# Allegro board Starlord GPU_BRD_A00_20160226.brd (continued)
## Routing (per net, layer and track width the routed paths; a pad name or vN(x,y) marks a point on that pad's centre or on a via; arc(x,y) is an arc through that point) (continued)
VCC1R05VIDEO_PEX_PLLVDD: length 11.2
  TOP w0.508: v2(17.95,59.36) 18.02,59.36 18.15,59.24 v1(20.36,59.24) 21.78,59.24 22.18,58.84 C7318.1 23.72,58.84 v2(24.04,58.52)
  BOTTOM w0.508: L7301.1 14.07,60.82 C7319.1 15.01,60.73 C7317.1 16.65,60.73 17.95,59.44 v2(17.95,59.36)
1D05V_PWR: length 19.8
  L3 w0.254: v2(3.44,63.3) 1.79,64.95 1.79,72.25 2.16,72.61 2.16,73.04 1.79,73.4 1.79,78.77 2.53,79.51 v2(3.22,79.51)
  BOTTOM w0.254: v2(3.22,79.51) PC8305.1 PR8303.1
  vias: v1(5.04,63.43)
1D05V_VGA_EN: length 99
  TOP w0.127: PR8310.2 C8308.2 36.59,3.58 v2(37.12,3.05) 37.15,3.08 37.71,3.08 v1(37.73,3.1)
  L3 w0.127: v2(1.44,72.75) 1.44,72.61 1.27,72.44 1.27,56.67 0.87,56.26 0.87,51.39 1.27,50.98 1.27,46.22 2.42,45.08 2.42,39.18 3.47,38.13 6.04,38.13 7.56,36.6 7.56,34.5 12.69,29.37 12.69,23.83 14.7,21.82 14.7,16.59 16.78,14.51 19.64,14.51 21.81,12.34 21.81,9.45 25.57,5.69 v2(25.57,5.36)
  L6 w0.127: v2(37.12,3.05) 36.16,3.05 35.74,2.63 28.3,2.63 v2(25.57,5.36)
  BOTTOM w0.127: v2(25.57,5.36) 25.57,5.54 25.52,5.59 R8305.2 ; PR8308.1 2.2,72.06 1.51,72.75 v2(1.44,72.75) ; PQ8301.2 37.07,3 v2(37.12,3.05)
1D05V_VGA_EN#:
  vias: v1(39.16,1.63)
1D05V_VGA_S0: length 87.2
  TOP w0.508: v2(37.2,4.75) 37.86,4.75 38.45,4.16 42.23,4.16 42.61,4.55 44.92,4.55 47.92,7.55 47.92,8.82 46.9,9.83 46.9,12.93 44.62,15.22 44.62,30.52 45.18,31.08 45.18,31.96 45.15,31.98 45.15,32.97 44.71,33.41 42.02,33.41 41.54,33.89 41.54,37.22 40.55,38.21 40.55,38.95 40.18,39.32 35.55,39.32 v2(35.32,39.09) ; C7312.1 24.22,55.41 v2(24.03,55.22)
  L4 w0.406: 22.94,57.9 23.98,56.86 v2(24.03,56.86)
  L4 w0.508: v2(32.86,40.69) 32.73,40.82 23.28,40.82 20.46,43.64 20.46,46.63 20.51,46.68 20.51,54.82 ; 21.56,57.9 22.94,57.9
  BOTTOM w0.508: L7601.1 35.22,39.63 35.32,39.53 v2(35.32,39.09) ; L7602.1 33.65,39.91 v2(32.86,40.69) ; PR8306.1 36.72,5.24 v2(37.2,4.75)
  BOTTOM w0.762: L7601.1 L7602.1
  vias: v1(18.2,61.78) v1(22.32,64.95) v2(22.39,65.97) v2(22.42,66.81) v2(23.21,65.09) v2(24.07,62.66) v2(24.04,61.82) v2(24.03,56.02) v3(11.5,61.62) v3(11.5,60.71) v3(11.55,63.6) v3(11.52,62.64) v3(17.47,66.17)
1D05V_VGA_S0_DISCHG: length 4.1
  BOTTOM w0.102: v1(34.64,2.62) 34.64,3.26 34.89,3.51 35.19,3.51 35.33,3.65 PQ8301.3 36.13,4.79 PR8306.2
1D05V_VGA_S0_PWRGD: length 81.6
  TOP w0.127: PR8320.2 4.17,73.27 4.74,72.7 v1(5.17,72.7) 8.02,72.7 8.3,72.98 v2(8.85,72.98)
  L3 w0.127: v2(8.85,72.98) 9.64,72.19 9.64,67.62 14.67,62.59 14.67,59.52 17.36,56.83 17.36,47.53 19.18,45.72 19.18,44.49 20.4,43.27 30.33,43.27 32.64,45.58 35.1,45.58 35.89,44.8 39.86,44.8 45.84,50.78 47.15,50.78 50.13,53.76 v2(50.13,58.68)
  BOTTOM w0.127: v2(50.13,58.68) 50.13,58.28 R8303.1 D8301.2
1D35V_PGOOD: length 1.3
  BOTTOM w0.127: TP8301.1 46.78,10.34 PR8321.1
1D35V_PWR:
  vias: v1(46.9,26.6)
1D35V_VGA_EN: length 58.4
  TOP w0.127: v2(43.3,10.74) 43.3,10.74 v1(43.3,11.31)
  L6 w0.127: v2(43.3,10.74) 43.3,10.92 44.39,12.01 44.39,28.25 43.44,29.2 43.44,32.76 45.02,34.34 45.02,36.46 43.75,37.72 43.75,39.09 v2(43.37,39.47)
  BOTTOM w0.127: R8303.2 R8304.1 52.23,55.68 D8301.3 51.3,54.5 51.3,53.39 51.91,52.78 PQ8308.2 51.91,51.72 51.06,50.87 50.98,50.87 50.86,50.76 50.86,48.93 51.7,48.09 51.7,44.71 48.35,41.35 45.51,41.35 43.63,39.47 v2(43.37,39.47) ; v2(43.3,10.74) 43.3,10.75 43.79,11.24 PR8322.1
1D35V_VGA_EN#: length 4
  BOTTOM w0.127: PQ8308.5 51.91,48.96 ; 51.91,48.96 PR8328.1 52,48.45 v1(52.54,47.91) ; 51.91,48.96 51.26,49.61 PQ8308.6
1D35V_VGA_S0: length 200.3
  TOP w0.203: v2(17.61,89.2) 17.2,89.6 VRAM3.P11
  TOP w0.305: 14.3,91.65 v2(14.31,91.65) 14.35,91.65 VRAM3.T14 ; v2(36.31,91.65) 36.35,91.65 VRAM2.B1
  TOP w0.356: VRAM2.K3 38.4,84.81 v2(38.8,85.2) ; v2(17.6,84.4) VRAM3.G11 VRAM3.F12 ; VRAM3.P3 23.58,89.6 v2(23.2,89.98) ; VRAM3.M3 23.6,88 v2(24,88.4) ; VRAM3.D1 25.36,81.6 25.65,81.31 v2(25.75,81.31) ; VRAM2.P11 v2(44.4,81.2) VRAM2.R10 v2(43.47,80.27) ; v2(18.41,82.02) 18.28,82.15 18.25,82.15 VRAM3.E10 ; VRAM3.C5 21.61,80.41 v2(21.61,80.39) ; v2(36.26,82.68) 36.78,83.2 VRAM2.M1 ; v2(25.85,89.68) 25.78,89.6 VRAM3.P1 ; VRAM2.C10 43.78,90.4 v2(43.35,90.82) ; 34.97,83.42 35.67,84.13 36.67,84.13 VRAM2.L1 37.2,84.4 ; v2(38.82,80.4) 38.42,80 VRAM2.T3 ; VRAM2.R5 40.41,80.39 v2(40.43,80.39) ; v2(16.02,84.41) 16.08,84.47 16.08,84.48 VRAM3.H12 ; VRAM2.G14 47.53,87.2 47.74,86.99 v2(47.74,86.95) ; v2(14.22,87.22) 14.24,87.2 VRAM3.L14 ; VRAM2.P1 36.73,81.6 v2(36.24,81.11) ; v2(17.6,87.6) 17.2,87.2 VRAM3.L11 ; v2(40.48,91.57) 40.48,90.88 VRAM2.C5 ; v2(13.75,87.96) 13.79,88 VRAM3.M14 ; VRAM2.G13 46.4,87.2 v2(46,86.8) 45.6,86.4 VRAM2.H12 ; VRAM2.G11 44.8,87.19 v2(44.4,86.79) ; v2(45.2,81.21) 45.59,81.6 VRAM2.P12 ; VRAM3.L4 22.8,87.19 v2(22.4,86.79) ; v2(36.27,79.48) 36.48,79.68 36.48,79.68 VRAM2.T1 ; v2(44.4,84.41) 44.4,84.4 VRAM2.L11 ; VRAM2.G2 37.6,87.2 v2(38,86.8) 38.4,86.4 VRAM2.H3 ; VRAM3.B14 14.48,79.68 14.48,79.68 v2(14.27,79.48) ; v2(39.62,88.41) 40,88.79 VRAM2.E5 ; VRAM2.M3 VRAM2.L4 v2(39.6,84.4) ; VRAM2.D12 45.59,89.6 v2(45.2,89.98) 45.17,89.95 45.15,89.95 VRAM2.D11 ; VRAM2.D1 36.2,89.6 v2(36.11,89.69) ; 37.2,84.4 37.6,84 VRAM2.L2 ; 37.2,84.4 v2(37.2,84.41) ; VRAM3.G1 25.39,84 v2(25.75,83.65) 25.72,83.65 25.27,83.2 VRAM3.F1 ; VRAM2.T12 45.58,80 v2(45.18,79.6) ; VRAM2.N5 40.25,82.15 v2(40.5,82.15) ; VRAM3.N5 21.57,88.37 v2(21.57,88.34) ; VRAM3.R10 18.38,90.78 v2(18.43,90.78) ; v2(43.33,88.55) 43.57,88.8 VRAM2.E10 ; v2(25.77,79.79) 25.68,79.89 25.53,79.89 25.42,80 VRAM3.B1 ; v2(16.8,82) 16.4,81.61 VRAM3.D12 ; VRAM2.F12 45.6,88 v2(46,88.4) ; v2(38,88.4) VRAM2.F3 ; VRAM3.E5 21.91,82.4 v2(21.48,82.83) ; VRAM2.D3 38.39,89.6 v2(37.99,89.2) ; VRAM3.G2 VRAM3.H3 23.6,84.8 23.21,84.41 23.21,84.41 v2(23.21,84.4) 23.2,84.4 VRAM3.G4 v2(23.2,83.6) VRAM3.F3 ; v2(47.74,79.53) 47.27,80 VRAM2.T14 ; VRAM3.P14 13.52,89.6 v2(13.41,89.49) ; VRAM2.D14 47.78,89.6 47.97,89.79 v2(47.99,89.79) ; VRAM3.N10 18,88.78 v2(17.6,88.37) ; VRAM3.D3 23.57,81.6 v2(23.18,81.21) ; VRAM3.M1 25.71,88 v2(25.79,87.91) ; v2(16.82,80.4) 16.42,80 VRAM3.B12 ; v2(18.43,80.39) 18.41,80.39 VRAM3.C10 ; v2(23.18,79.61) 23.18,79.61 23.58,80 VRAM3.B3 ; VRAM3.P12 16.39,89.6 v2(15.99,89.2) ; v2(21.56,90.77) 21.93,90.4 VRAM3.R5 ; VRAM2.F14 48.12,88 v2(48.2,88.08) ; v2(14.26,82.68) 14.78,83.2 VRAM3.F14 VRAM3.G14 15.2,84.4 ; v2(47.79,82.07) 47.32,81.6 VRAM2.P14 ; 15.2,84.4 15.6,84 VRAM3.G13 ; 15.2,84.4 v2(15.2,84.41) ; VRAM2.L11 v2(45.2,83.6) VRAM2.M12 ; VRAM2.L11 VRAM2.K12 VRAM2.L13 46.44,84 46.58,84.13 47.07,84.13 VRAM2.L14 47.58,84 47.8,83.78 v2(47.8,83.4) 47.79,83.42 47.47,83.42 47.25,83.2 VRAM2.M14 ; VRAM3.K3 23.6,86.4 v2(24,86.8) 24.4,87.2 VRAM3.L2 VRAM3.L1 25.62,87.2 v2(25.79,87.02) ; VRAM3.K12 16.4,86.4 v2(16,86.8) 15.6,87.2 VRAM3.L13 ; VRAM3.D11 v2(17.59,81.21) ; v2(39.6,87.6) 39.2,87.2 VRAM2.G4 ; v2(36.22,87.22) 36.24,87.2 VRAM2.G1 ; VRAM3.D14 14.73,81.6 v2(14.24,81.11) ; VRAM2.P3 38.4,81.61 v2(38.8,82) ; VRAM2.N10 v2(43.46,81.86) ; VRAM2.F1 35.78,88 35.74,88.04 v2(35.68,88.04) ; v2(16,88.4) VRAM3.M12
  TOP w0.406: v2(37.35,65.1) 37.94,64.52 38.12,64.52 38.31,64.33 ; VRAM3.T1 25.42,91.42 25.83,91.42 v2(25.84,91.43) ; VRAM3.T3 23.6,91.2 23.2,91.6 v2(23.18,91.6) ; v2(48.21,91.52) 48.11,91.42 47.42,91.42 VRAM2.B14 ; VRAM3.T12 16.43,91.2 v2(16.83,91.6) ; v2(45.18,91.6) 45.2,91.6 45.6,91.2 VRAM2.B12 ; VRAM2.B3 38.43,91.2 v2(38.83,91.6)
  TOP w0.508: 12.61,91.85 13.97,91.85 14.17,91.65 14.3,91.65 ; 42.37,68.24 42.37,65.26 41.44,64.33 R7505.2 38.31,64.33 ; v2(25.79,87.02) 25.97,87.02 27.24,88.29 ; 13.04,79.48 v2(14.27,79.48) ; 13.35,82.12 13.91,82.68 v2(14.26,82.68) ; 49.05,83.4 v2(47.8,83.4) ; v2(29.86,64.37) 30.11,64.11 C7507.1 ; C7502.1 36.53,58.47 v2(36.56,58.5) ; v2(31.54,85.68) R7516.2 R7812.2 ; 13.2,81.11 v2(14.24,81.11) ; v2(36.22,87.22) 34.78,87.22 ; 34.45,88.04 v2(35.68,88.04) ; v2(13.75,87.96) 13.72,87.99 13.23,87.99 12.79,88.42 ; 26.67,89.68 v2(25.85,89.68) ; 12.39,89.49 v2(13.41,89.49) ; 34.79,92.15 35.8,92.15 v2(36.31,91.65) ; 49.29,81.51 48.33,81.51 47.79,82.05 v2(47.79,82.07) ; v2(47.74,79.53) 49.11,79.53 ; 26.53,81.31 v2(25.75,81.31) ; 26.95,91.43 v2(25.84,91.43) ; v2(25.79,87.91) 25.79,87.94 26.4,88.55 26.4,88.57 26.79,88.95 ; v2(36.27,79.48) 35.04,79.48 ; v3(49.7,94.67) 50.21,94.16 C7822.1 ; v2(30.78,85.97) 30.66,85.86 R7524.2 29.41,85.86 29.38,85.88 R7910.2 ; R7806.1 51.4,89.6 R7805.1 52.99,89.6 v2(53,89.61) ; 26.31,79.79 v2(25.77,79.79) ; v2(36.11,89.69) 34.66,89.69 ; v2(36.24,81.11) 35.04,81.11 ; v2(25.75,83.65) 27.22,83.65 ; 35.32,82.68 v2(36.26,82.68)
  BOTTOM w0.203: GPU1.H24 35.26,66.55 34.87,66.94 34.87,67.45 35.26,67.85 GPU1.H26 ; VRAM3.P11 17.2,89.6 v2(17.61,89.2)
  BOTTOM w0.305: VRAM3.M14 14.61,88 14.57,87.97 13.76,87.97 v2(13.75,87.96) ; VRAM2.D14 47.78,89.6 47.97,89.79 v2(47.99,89.79) ; v2(32.35,65.99) 32.76,66.4 GPU1.L24 ; VRAM2.F1 35.78,88 35.74,88.04 v2(35.68,88.04) ; GPU1.E26 38.16,68.41 v2(38.19,68.41) ; v2(25.85,89.68) 25.78,89.6 VRAM3.P1 ; GPU1.L26 32.78,68.33 32.9,68.45 32.9,69.22 v2(32.9,69.22)
  BOTTOM w0.33: VRAM3.F14 14.78,83.2 v2(14.26,82.68) ; v2(36.26,82.68) 36.78,83.2 VRAM2.M1
  BOTTOM w0.356: v2(36.22,87.22) 36.24,87.2 VRAM2.G1 ; VRAM3.L1 25.37,87.2 25.46,87.11 25.58,87.11 25.67,87.02 v2(25.79,87.02) ; v2(43.47,80.27) VRAM2.R10 ; v2(18.41,82.02) 18.28,82.15 18.25,82.15 VRAM3.E10 ; VRAM3.E5 21.91,82.4 v2(21.48,82.83) ; v2(14.27,79.48) 14.48,79.68 14.48,79.68 VRAM3.B14 ; VRAM2.M3 VRAM2.L4 v2(39.6,84.4) ; VRAM2.G13 46.4,87.2 v2(46,86.8) 45.6,86.4 VRAM2.H12 ; VRAM3.C10 18.41,80.39 v2(18.43,80.39) ; VRAM3.D3 23.6,81.6 23.21,81.21 v2(23.18,81.21) ; GPU1.E23 37.35,65.15 v2(37.35,65.1) ; VRAM3.L4 22.8,87.19 v2(22.4,86.79) ; v2(16,88.4) VRAM3.M12 ; v2(48.21,91.52) 47.94,91.52 47.85,91.43 47.43,91.43 VRAM2.B14 ; VRAM3.N5 21.57,88.37 v2(21.57,88.34) ; VRAM3.G4 23.2,84.4 v2(23.21,84.4) 23.21,84.41 23.21,84.41 VRAM3.H3 VRAM3.G2 ; VRAM2.P3 38.4,81.61 v2(38.8,82) ; VRAM2.P12 45.59,81.6 v2(45.2,81.21) 44.8,81.6 VRAM2.P11 v2(44.4,81.2) ; v2(47.74,79.53) 47.67,79.61 47.59,79.61 VRAM2.T14 ; v2(36.31,91.65) 36.39,91.57 36.43,91.57 VRAM2.B1 ; v2(16.8,82) 16.4,81.61 VRAM3.D12 ; VRAM2.N5 40.25,82.15 v2(40.5,82.15) ; v2(46,88.4) 45.6,88 VRAM2.F12 ; v2(44.4,84.41) 44.4,84.4 VRAM2.L11 VRAM2.K12 VRAM2.L13 ; VRAM3.H12 16.08,84.48 16.08,84.47 v2(16.02,84.41) ; VRAM2.T3 38.42,80 v2(38.82,80.4) ; VRAM2.P1 36.73,81.6 v2(36.24,81.11) ; v2(21.61,80.39) 21.61,80.41 VRAM3.C5 ; v2(17.6,88.37) 18,88.78 VRAM3.N10 ; v2(21.56,90.77) 21.93,90.4 VRAM3.R5 ; VRAM3.F12 VRAM3.G11 v2(17.6,84.4) ; v2(14.22,87.22) 14.24,87.2 VRAM3.L14 ; VRAM2.E10 43.57,88.8 v2(43.33,88.55) ; v2(39.62,88.41) 40,88.79 VRAM2.E5 ; VRAM3.K12 16.4,86.4 v2(16,86.8) 15.6,87.2 VRAM3.L13 ; v2(23.18,79.61) 23.18,79.61 23.58,80 VRAM3.B3 ; VRAM2.L14 47.36,84 47.8,83.56 v2(47.8,83.4) 47.79,83.42 47.47,83.42 47.25,83.2 VRAM2.M14 ; v2(40.48,91.57) 40.48,91.56 40.48,90.88 VRAM2.C5 ; v2(23.2,89.98) 23.22,89.98 VRAM3.P3 ; v2(45.18,79.6) 45.58,80 VRAM2.T12 ; v2(47.79,82.07) 47.32,81.6 VRAM2.P14 ; v2(25.77,79.79) 25.77,79.79 25.41,79.79 VRAM3.B1 ; v2(17.6,87.6) 17.2,87.2 VRAM3.L11 ; VRAM3.P14 14.75,89.55 13.68,89.55 13.62,89.49 v2(13.41,89.49) ; VRAM3.D14 14.73,81.6 v2(14.24,81.11) ; VRAM2.F14 47.4,88 47.47,87.92 48.04,87.92 v2(48.2,88.08) ; v2(16.82,80.4) 16.42,80 VRAM3.B12 ; VRAM3.D11 v2(17.59,81.21) ; VRAM3.T14 14.43,91.57 14.39,91.57 v2(14.31,91.65) ; VRAM2.N10 v2(43.46,81.86) ; v2(45.2,83.6) VRAM2.M12 ; v2(25.84,91.43) 25.83,91.42 25.42,91.42 VRAM3.T1 ; VRAM3.F1 25.27,83.2 25.72,83.65 v2(25.75,83.65) 25.39,84 VRAM3.G1 ; v2(40.43,80.39) 40.41,80.39 VRAM2.R5 ; 15.2,84.4 VRAM3.G14 ; 15.2,84.4 v2(15.2,84.41) ; 15.2,84.4 15.6,84 VRAM3.G13 ; VRAM2.D3 38.39,89.6 v2(37.99,89.2) ; VRAM3.R10 18.38,90.78 v2(18.43,90.78) ; VRAM3.K3 23.6,86.4 v2(24,86.8) 24.4,87.2 VRAM3.L2 ; VRAM3.M3 23.6,88 v2(24,88.4) ; v2(38,88.4) VRAM2.F3 ; VRAM2.D11 45.15,89.95 45.17,89.95 v2(45.2,89.98) 45.59,89.6 VRAM2.D12 ; v2(36.11,89.69) 36.2,89.6 VRAM2.D1 ; v2(25.75,81.31) 25.65,81.31 25.36,81.6 VRAM3.D1 ; v2(25.79,87.91) 25.71,88 25.41,88 VRAM3.M1 ; v2(44.4,86.79) 44.8,87.19 VRAM2.G11 ; v2(40.76,68.61) 40.76,68.56 40.2,68 GPU1.B26 GPU1.C25 ; v2(35.38,69.49) 35.37,69.48 35.37,68.41 35.26,68.29 GPU1.H26 ; VRAM3.P12 16.39,89.6 v2(15.99,89.2) ; v2(23.2,83.6) VRAM3.F3 ; VRAM2.L2 37.6,84 37.2,84.4 ; VRAM2.K3 38.4,84.81 v2(38.8,85.2) ; v2(47.74,86.95) 47.61,87.09 47.53,87.09 47.42,87.2 VRAM2.G14 ; VRAM2.G4 39.2,87.2 v2(39.6,87.6) ; VRAM2.C10 43.78,90.4 v2(43.35,90.82) ; v2(36.27,79.48) 36.48,79.68 36.48,79.68 VRAM2.T1 ; VRAM2.H3 38.4,86.4 v2(38,86.8) 37.6,87.2 VRAM2.G2 ; 37.2,84.4 VRAM2.L1 ; 37.2,84.4 v2(37.2,84.41)
  BOTTOM w0.406: v2(38.83,91.6) 38.43,91.2 VRAM2.B3 ; VRAM2.B12 45.2,91.6 v2(45.18,91.6) ; v2(23.18,91.6) 23.2,91.6 VRAM3.T3 ; VRAM3.T12 16.43,91.2 v2(16.83,91.6)
  BOTTOM w0.508: v3(49.7,94.67) 50.21,94.16 C7822.1
  vias: v1(45.65,30.8) v1(49.9,75.42) v1(50.56,29.65) v1(51.81,39.88) v1(51.88,35.69) v1(52.01,63.81) v1(52.52,67.26) v2(13.25,94.67) v2(14.01,94.67) v2(25.85,63.48) v2(26.66,63.48) v2(33.19,64.32) v2(34.02,64.36) v2(34.99,62.11) v2(35.63,61.85) v2(35.63,59.24) v2(35.63,58.37) v3(11.27,75.44) v3(17.62,93.87) v3(31.23,77.04) v3(31.77,76.25) v3(46.47,30.25) v3(46.68,29.39) v3(47.34,30.25) v3(47.69,29.39) v3(48.05,59.24) v3(48.2,30.25) v3(48.66,29.42) v3(48.81,94.67) v3(49.06,59.24) v3(49.09,30.25) v3(50.31,42.17) v3(51.04,43.03) v3(51.22,42.19) v3(51.76,43.59) v3(52.16,42.27) v3(52.44,44.22) v3(52.59,43.28) v3(52.95,75.19) v3(52.95,73.46) v3(53,74.32) v3(53,72.6)
1D35V_VGA_S0_DISCHG: length 2.4
  BOTTOM w0.102: PQ8308.3 52.56,52.64 52.06,53.14 v1(52.06,53.27) 52.12,53.33 PR8329.2
3D3V_AUX_S5: length 105.7
  TOP w0.254: v1(39.16,4.8) 39.76,4.8 v2(39.77,4.8)
  TOP w0.508: v2(39.66,7.41) 39.8,7.41 PR8319.2
  L3 w0.508: v2(42.87,38.92) 42.59,39.2 42.59,39.28 42.21,39.65 41.51,39.65 41.18,39.32 35.99,39.32 35.58,39.73 35.06,39.73 34.59,39.26 12.51,39.26 10.59,41.18 10.59,45.28 8.75,47.12 8.75,50.6 v2(8.35,51) ; v2(39.77,4.8) 39.77,7.31 v2(39.66,7.41)
  L6 w0.508: v2(39.66,7.41) 39.66,7.41 41.62,9.37 41.62,10.88 42.41,11.66 43.26,11.66 43.86,12.26 43.86,28.15 42.99,29.02 42.99,33.23 43.22,33.46 43.22,38.56 v2(42.87,38.92)
  BOTTOM w0.305: GPU3.F10 7.76,51 v2(8.35,51)
  BOTTOM w0.508: v2(39.77,4.8) 39.77,4.6 39.69,4.52 PR8307.1 ; PR8328.2 53.33,48.43 53.33,42.35 51.76,40.77 45.64,40.77 43.66,38.79 42.99,38.79 v2(42.87,38.92) ; v2(39.66,7.41) PR8315.2 PR8319.2
3D3V_S0: length 17.8
  TOP w0.254: v1(39.36,38.69) v2(39.92,38.69)
  L3 w0.508: v3(44.42,31.52) 44.31,31.52 44.26,31.47 43.78,31.47 43.3,30.99 43.3,20.27 43.53,20.04 43.53,17.86 v2(43.12,17.45)
  BOTTOM w0.508: v2(39.92,38.69) 39.92,38.74 40.02,38.84 40.02,39.3 39.73,39.59 R7648.2 ; PR8325.2 v2(43.12,17.45)
  vias: v3(1.72,42.55) v3(1.72,41.71) v3(1.72,40.87) v3(1.72,40.03) v3(6.01,80.39) v3(6.1,81.23) v3(6.89,80.34) v3(7.03,81.17) v3(7.69,40.06) v3(7.7,41.02) v3(46.17,33.18) v3(46.17,32.29) v3(47.36,32.46) v3(48.45,32.34)
3D3V_VGA_CT_1: length 1.7
  BOTTOM w0.203: 48.83,37.09 U8301.12
  BOTTOM w0.254: 48.83,37.09 48.89,37.14 48.89,37.73 48.88,37.75 48.88,38.02 C8302.1
3D3V_VGA_S0: length 99.1
  TOP w0.254: R7635.1 42.73,56.99 43.06,56.66 43.21,56.66 43.65,56.21 43.65,55.24 45.24,53.66
  TOP w0.508: R7635.1 42.28,56.2 R7618.1 R7620.1 ; v2(35.02,3.97) 35.04,3.99 35.04,4.02 35.41,4.39 35.69,4.39 PR8310.1 PR8318.1 ; v3(49.77,38.77) 49.27,39.28 49.27,39.96 47.87,41.35 43.94,41.35 42.7,42.6 42.2,42.6 ; C7703.1 35.79,51.15 C7728.1 C7729.1 35.79,53.28 v2(35.63,53.44) 35.54,53.53 35.36,53.53 34.97,53.93 34.97,53.97 C7734.1 ; v2(51.98,53.95) 51.2,53.17 45.73,53.17 45.24,53.66 42.89,51.31 42.89,49.48 42.16,48.76 42.16,42.64 42.2,42.6 ; 42.2,42.6 v2(41.24,42.6)
  L3 w0.508: v2(44.41,42.37) 42.93,42.37 42.9,42.4 42.37,42.4 42.35,42.37 41.47,42.37 v2(41.24,42.6)
  L6 w0.508: v3(49.82,37.72) 49.82,34.14 50.05,33.91 50.05,32.7 50.05,29.01 49.49,28.45 46.4,28.45 45.94,27.99 45.94,11.49 45.18,10.73 45.18,8.95 44.83,8.6 44.83,7.08 43.37,5.62 42.29,5.62 40.82,4.14 37.49,4.14 37.06,3.71 35.27,3.71 v2(35.02,3.97)
  BOTTOM w0.356: GPU1.G9 35.63,53.45 v2(35.63,53.44) 35.78,53.44 36.08,53.14 GPU1.G8
  BOTTOM w0.508: PR8256.1 34.33,5.87 35.01,5.19 35.04,5.16 35.04,3.99 v2(35.02,3.97) ; v2(41.24,42.6) 40.86,42.22 R7605.1 ; PR8329.1 52.25,54.22 v2(51.98,53.95)
  vias: v1(49.32,38.15)
3D3V_VGA_S0_DISCHG: length 10.5
  TOP w0.102: v2(43.22,6.37) 43.21,6.37 v1(42.48,5.64) 42.07,5.23 PR8318.2
  BOTTOM w0.102: PQ8307.3 42.42,8.85 42.97,8.31 42.97,6.62 v2(43.22,6.37)
27MHZ_IN: length 12.2
  BOTTOM w0.089: X7601.1 47.25,56.47 46.24,56.47 45.88,56.83 45.88,57.44 45.45,57.88 C7607.2 R7603.1 44.31,57.8 43.86,57.35 43.86,56 43.24,55.38 40.48,55.38 40.38,55.28 39.94,55.28 39.6,55.62 GPU1.C11
27MHZ_OUT: length 5.5
  BOTTOM w0.089: R7603.2 R7604.2 44.3,56.1 43.34,55.14 40.58,55.14 40.45,55.02 40.44,55.02 GPU1.B10
27MHZ_OUT_R: length 2.5
  BOTTOM w0.14: X7601.3 46.64,55.21 C7608.2 R7604.1
AC_PRESENT: length 1.5
  BOTTOM w0.102: D7601.K 36.77,38.79 TP7608.1
CLK_PCIE_VGA: length 34.8
  TOP w0.114: 2.9,50.44 1.13,52.2 1.13,56.25 2.95,58.07 3.22,58.07 3.44,58.3 v2(3.44,58.49) ; 2.9,50.44 5.4,47.93 11.75,47.93 13.07,49.25 16.03,49.25 18.42,51.64 21.75,51.64 22.18,52.08 22.18,52.38 21.84,52.73 v2(21.6,52.73) ; 2.9,50.44 v1(3.01,50.55)
  BOTTOM w0.114: GPU3.B3 3.55,58.38 v2(3.44,58.49) ; v2(21.6,52.73) 21.33,52.73 21.2,52.86 GPU1.AE8
CLK_PCIE_VGA#: length 34.8
  TOP w0.114: v1(4,48.8) 4.1,48.89 ; 4.1,48.89 5.3,47.69 11.85,47.69 13.17,49.01 16.13,49.01 18.52,51.4 21.85,51.4 22.42,51.98 v2(22.42,52.73) ; 4.1,48.89 0.89,52.1 0.89,56.35 2.81,58.27 v2(2.81,58.5)
  BOTTOM w0.114: GPU3.B2 2.95,58.35 v2(2.81,58.5) ; GPU1.AD8 22.41,52.73 22.42,52.73 v2(22.42,52.73)
CLKREQ_PEG#0: length 43.1
  L3 w0.102: v2(6.8,60.58) 6.8,59.77 6.47,59.44 2.25,59.44 1.51,58.7 1.51,56.57 1.11,56.16 1.11,51.49 1.51,51.08 1.51,46.32 2.8,45.03 2.8,39.51 3.77,38.54 6.16,38.54 v2(8.27,36.43)
  BOTTOM w0.102: v2(8.27,36.43) 8.6,36.1 8.6,35.4 v1(7.77,34.57) 6.91,33.71 6.91,32.25 8,31.16 Q7301.D 8.51,31.09 R7305.1 ; GPU3.A9 7.15,60.22 v2(6.8,60.58)
CPU_RXN_C_DGPU_TXN0: length 17.3
  TOP w0.114: v2(12.84,50.99) 12.84,51.83 13.5,52.49 15.31,52.49 16.36,53.54 17.1,53.54 17.75,52.89 17.97,52.89 C7302.1
  BOTTOM w0.114: v1(12.94,51.64) 13.11,51.64 ; 13.11,51.64 13.11,52.23 12.25,53.09 9.87,53.09 8.4,51.62 6.89,51.62 6.63,51.88 6.63,52.12 6.55,52.2 GPU3.E8 ; 13.11,51.64 13.11,51.26 v2(12.84,50.99)
CPU_RXN_C_DGPU_TXN1: length 21.6
  TOP w0.114: v1(5.27,49.69) 5.41,49.69 ; 5.41,49.69 5.41,49.44 6.42,48.44 11.55,48.44 12.34,49.24 12.34,52.39 13.53,53.57 14.37,53.57 15.36,54.56 16.78,54.56 17.08,54.26 18.04,54.26 C7304.1 ; 5.41,49.69 5.41,50.25 4.68,50.98 v2(4.68,51.79)
  BOTTOM w0.114: GPU3.E5 4.75,51.94 4.68,51.87 v2(4.68,51.79)
CPU_RXN_C_DGPU_TXN2: length 20.9
  TOP w0.114: C7306.1 17.94,56.37 12.41,56.37 9.72,53.68 9.72,52.23 10.33,51.62 10.79,51.62 v2(10.99,51.41)
  BOTTOM w0.114: 10.05,50.98 8.38,49.32 5.92,49.32 5.5,49.74 5.5,50.39 5.35,50.53 GPU3.F6 ; 10.05,50.98 v1(10.18,50.85) ; 10.05,50.98 10.48,51.41 v2(10.99,51.41)
CPU_RXN_C_DGPU_TXN3: length 26.5
  TOP w0.114: v1(8.83,53.17) 8.97,53.17 ; 8.97,53.17 8.97,54 13.12,58.15 17.94,58.15 C7308.1 ; 8.97,53.17 8.97,51.36 10.27,50.07 10.86,50.07 v2(11.04,49.89)
  BOTTOM w0.114: GPU3.F3 3.55,50.52 3.72,50.35 3.72,49.41 4.55,48.58 9.73,48.58 v2(11.04,49.89)
CPU_RXP_C_DGPU_TXP0: length 17.3
  TOP w0.114: v2(13.64,50.99) 13.54,50.99 13.08,51.45 13.08,51.73 13.6,52.25 15.41,52.25 16.46,53.3 17,53.3 17.65,52.65 17.97,52.65 C7301.1
  BOTTOM w0.114: 12.13,53.33 9.77,53.33 8.3,51.86 6.99,51.86 6.87,51.98 6.87,52.14 7.15,52.43 GPU3.E9 ; 12.13,53.33 v1(12.13,53.5) ; 12.13,53.33 12.35,53.33 13.35,52.33 13.35,51.29 v2(13.64,50.99)
CPU_RXP_C_DGPU_TXP1: length 21.6
  TOP w0.114: v1(6.95,48.82) 6.95,48.68 ; 6.95,48.68 11.45,48.68 12.1,49.34 12.1,52.49 13.43,53.81 14.27,53.81 15.26,54.8 16.88,54.8 17.18,54.5 17.85,54.5 C7303.1 ; 6.95,48.68 6.52,48.68 5.65,49.54 5.65,50.35 4.93,51.07 4.93,51.42 5.3,51.79 v2(5.4,51.79)
  BOTTOM w0.114: GPU3.E6 5.35,52.43 5.24,52.32 5.24,51.95 v2(5.4,51.79)
CPU_RXP_C_DGPU_TXP2: length 20.7
  TOP w0.114: v2(10.99,52.05) 10.81,51.87 10.42,51.87 9.96,52.33 9.96,53.58 12.51,56.13 17.94,56.13 C7305.1
  BOTTOM w0.114: v2(10.99,52.05) 10.99,52.38 10.86,52.51 v1(10.66,52.51) 10.43,52.51 10.29,52.36 10.29,51.56 8.28,49.56 6.02,49.56 5.74,49.84 5.74,50.33 5.95,50.54 GPU3.F7
CPU_RXP_C_DGPU_TXP3: length 26.5
  TOP w0.114: 9.21,51.77 9.21,53.9 13.22,57.91 17.94,57.91 C7307.1 ; 9.21,51.77 v1(9.34,51.77) ; 9.21,51.77 9.21,51.46 10.37,50.31 10.8,50.31 v2(11.01,50.52)
  BOTTOM w0.114: GPU3.F4 4.15,50.49 3.97,50.3 3.97,49.51 4.65,48.82 9.63,48.82 10.57,49.76 10.57,50.78 10.7,50.9 10.88,50.9 11.01,50.78 v2(11.01,50.52)
DCBATOUT: length 16.9
  TOP w0.508: v2(26.56,1.48) 26.56,2.87 24.68,4.75 24.57,4.75 22.66,6.66 22.66,8.18 21.86,8.98 21.86,12.02 21.53,12.35 21.53,13.83 PU8206.4
  BOTTOM w0.508: PR8202.1 27.3,2.55 EC9703.1 26.53,1.5 v2(26.56,1.48)
  vias: v1(4.74,33.84) v1(10.07,31.42) v1(15.84,28.93) v1(16.04,15.68) v1(16.55,20.5) v1(19.17,15.29) v1(39.92,15.68) v1(47.89,8.64) v3(2.74,36.36) v3(3.09,35.49) v3(3.72,36.38) v3(4.1,35.49) v3(4.74,36.38) v3(5.12,35.49) v3(5.63,36.38) v3(6.14,35.36) v3(6.64,36.38) v3(17.44,18.09) v3(17.44,17.07) v3(17.44,15.93) v3(18.58,17.07) v3(18.58,15.93) v3(18.71,18.09) v3(20.11,17.2) v3(20.11,16.31) v3(20.11,15.4) v3(38.85,17.45) v3(38.85,16.56) v3(38.88,15.68) v3(38.88,14.76) v3(38.88,13.8) v3(45.89,8.74) v3(46.78,8.74) v3(50.28,8.36) v3(51.15,8.33)
DGPU_HOLD_RST#: length 34.7
  L3 w0.127: v2(18.83,41.66) 18.83,41.77 17.8,42.81 17.8,44.92 14.77,47.95 13.38,47.95 12.08,49.25 12.08,52.12 11.67,52.53 9.89,52.53 8.98,53.44 7.68,53.44 7.13,54 7.13,56.49 6.37,57.25 4.03,57.25 3.06,56.29 3.06,54.79 2.56,54.28 1.92,54.28 1.82,54.18 v2(1.8,54.18)
  BOTTOM w0.127: GPU3.D1 1.89,54.28 v2(1.8,54.18) ; v1(19.57,38.87) 19.92,39.21 R7304.1 19.92,41.14 U7301.1 19.19,41.25 18.84,41.61 18.84,41.66 v2(18.83,41.66)
DGPU_PWR_EN: length 102
  TOP w0.127: PR8331.1 36.96,6.65 v2(36.49,6.18) 36.46,6.2 v1(35.8,6.2)
  L3 w0.127: v2(1.8,56.16) 1.82,56.16 1.99,55.99 2.4,55.99 3.92,57.51 6.47,57.51 7.43,56.55 7.43,54.05 7.79,53.7 9.08,53.7 10,52.78 11.78,52.78 12.33,52.23 12.33,49.35 13.48,48.2 14.87,48.2 18.05,45.03 18.05,42.92 18.62,42.35 18.78,42.35 19.9,41.23 27.14,41.23 27.68,41.76 30.5,41.76 31.35,42.61 37.32,42.61 38.81,41.11 40.44,41.11 40.99,41.66 v2(42.61,41.66)
  L6 w0.127: v2(36.49,6.18) 39.07,6.18 39.45,6.55 39.45,6.57 39.85,6.97 39.85,6.97 40.11,7.23 43.03,10.15 43.33,10.15 43.97,10.79 43.97,11.23 44.64,11.9 44.64,29.68 43.87,30.46 43.87,32.74 45.3,34.18 45.3,36.53 44.01,37.82 44.01,40.08 42.64,41.46 42.64,41.63 v2(42.61,41.66)
  BOTTOM w0.127: PQ8306.2 36.57,6.1 v2(36.49,6.18) 36.38,6.06 PR8260.1 ; GPU3.C1 1.96,56 v2(1.8,56.16)
DGPU_PWR_EN#: length 6.3
  BOTTOM w0.102: 40.63,6.12 40.73,6.23 40.73,6.77 41.09,7.12 41.09,8.42 PR8317.1 ; 40.63,6.12 40.63,5.8 40.27,5.45 ; 40.63,6.12 39.94,6.12 PQ8306.5 ; 40.27,5.45 40.87,4.85 v1(41.11,4.85) ; 40.27,5.45 PQ8306.6
DGPU_PWR_EN_R: length 36.8
  TOP w0.127: v2(41.29,5.67) 41.2,5.76 R8306.1 C8310.1 PR8331.2 ; v1(47.13,33.91) 47.13,33.28 v2(47.16,33.25)
  L6 w0.127: v2(41.29,5.67) 40.8,6.16 40.8,7.55 43.14,9.9 43.44,9.9 44.22,10.68 44.22,11.13 44.95,11.85 44.95,30.26 46.81,32.12 46.81,32.91 v2(47.16,33.25)
  BOTTOM w0.127: v2(47.16,33.25) 47.23,33.33 47.54,33.33 48.03,33.82 U8301.5
DGPU_PWROK: length 67
  TOP w0.127: v1(25.21,8.21) 25.21,7.62 v2(25.24,7.6)
  L3 w0.127: v2(2.15,48.24) 2.39,48 6.35,48 7.66,46.69 7.66,43.71 7.39,43.45 7.39,42.74 8.75,41.38 8.75,33.66 12.97,29.45 12.97,24.13 14.95,22.15 14.95,16.69 16.88,14.76 19.75,14.76 22.06,12.45 22.06,9.58 23.43,8.21 24.65,8.21 25.24,7.62 v2(25.24,7.6)
  L6 w0.127: v2(1.82,53.52) 1.85,53.5 1.97,53.5 2.26,53.2 2.26,51.4 1.92,51.05 1.92,48.47 v2(2.15,48.24)
  BOTTOM w0.127: PU8201.13 26.8,6.55 PR8203.2 26.4,6.94 25.52,6.94 R8305.1 25.52,7.32 v2(25.24,7.6) ; v2(1.82,53.52) 1.84,53.52 1.92,53.6 2.73,53.6 2.95,53.82 GPU3.D2
DGPU_RXN_C_CPU_TXN0: length 22.7
  L6 w0.14: v2(5.23,60.58) 5.47,60.83 5.47,61.1 5.86,61.48 9.1,61.48 9.88,60.7 9.88,60.09 12.04,57.93 13.92,57.93 16.29,55.56 16.29,52.4 16.46,52.23 16.48,52.23 16.48,52.23 v2(16.49,52.23)
  BOTTOM w0.114: v2(5.23,60.58) 5.48,60.34 5.48,59.94 5.35,59.82 GPU3.A6 ; v1(17.06,52.23) 17.06,52.09 ; 17.06,52.09 19.39,52.09 GPU1.AG7 ; 17.06,52.09 16.63,52.09 v2(16.49,52.23)
DGPU_RXN_C_CPU_TXN1: length 25.4
  L6 w0.14: v2(14.57,53.14) 14.8,53.37 14.8,55.51 13.54,56.76 11.66,56.76 9.11,59.31 4.46,59.31 4.04,59.73 4.04,59.98 3.9,60.13 v2(3.56,60.13)
  BOTTOM w0.114: v2(3.56,60.13) 3.55,60.12 GPU3.A3 ; 14.81,53.7 14.81,54.1 15.23,54.52 16.19,54.52 17.83,52.89 20.15,52.89 20.39,52.65 21.02,52.65 21.15,52.52 21.15,52.35 GPU1.AE7 ; 14.81,53.7 14.81,53.38 v2(14.57,53.14) ; 14.81,53.7 v1(14.67,53.7)
DGPU_RXN_C_CPU_TXN2: length 19.3
  L6 w0.14: v2(6.69,58.4) 6.69,58.27 7.08,57.89 7.41,57.89 7.65,57.65 9.65,57.65 11.37,55.93 12.79,55.93 13.53,55.2 13.53,54.57 v2(13.25,54.28)
  BOTTOM w0.114: GPU1.AF9 20.05,53.63 18.19,53.63 16.17,55.65 13.99,55.65 13.58,55.25 13.58,54.94 ; v2(13.25,54.28) 13.58,54.62 13.58,54.94 ; 13.58,54.94 v1(13.43,54.94) ; GPU3.B8 6.55,58.26 v2(6.69,58.4)
DGPU_RXN_C_CPU_TXN3: length 20.8
  L6 w0.14: v2(4.76,58.5) 4.89,58.37 4.89,57.86 5.27,57.48 6.29,57.48 6.92,56.86 9.33,56.86 11.04,55.15 11.72,55.15 11.93,54.94 v2(11.93,54.28)
  BOTTOM w0.114: 13.4,56.56 13.12,56.56 11.93,55.36 v2(11.93,54.28) ; 13.4,56.56 v1(13.4,56.7) ; 13.4,56.56 16.35,56.56 18.4,54.5 19.32,54.5 GPU1.AG10 ; v2(4.76,58.5) 4.75,58.49 GPU3.B5
DGPU_RXP_C_CPU_TXP0: length 22.5
  L6 w0.14: v2(16.48,51.59) 16.48,51.59 16.02,52.05 16.02,55.45 13.81,57.66 11.93,57.66 9.61,59.97 9.61,60.59 8.99,61.22 5.97,61.22 5.74,60.99 5.74,60.88 v2(5.98,60.63)
  BOTTOM w0.114: v2(5.98,60.63) 5.98,60.61 5.72,60.34 5.72,59.96 5.95,59.72 GPU3.A7 ; GPU1.AG6 19.26,51.84 16.73,51.84 v2(16.48,51.59)
DGPU_RXP_C_CPU_TXP1: length 25.4
  L6 w0.14: v2(3.6,60.79) 3.62,60.79 4.12,60.29 4.31,60.09 4.31,59.84 4.57,59.58 9.22,59.58 11.77,57.03 13.65,57.03 15.06,55.62 15.06,53.28 v2(15.2,53.14)
  BOTTOM w0.114: GPU3.A4 4.15,60.23 v2(3.6,60.79) ; v2(15.2,53.14) 15.2,53.17 15.05,53.32 15.05,54 15.33,54.28 16.09,54.28 16.8,53.57 ; v1(16.68,53.44) 16.8,53.57 ; 16.8,53.57 17.73,52.65 20.05,52.65 GPU1.AF7
DGPU_RXP_C_CPU_TXP2: length 19.4
  L6 w0.14: v2(13.93,54.28) 13.79,54.42 13.79,55.31 12.9,56.2 11.48,56.2 9.77,57.92 7.76,57.92 7.33,58.35 v2(7.33,58.4)
  BOTTOM w0.114: 15.76,55.41 14.09,55.41 13.82,55.15 13.82,54.42 13.93,54.31 v2(13.93,54.28) ; 15.76,55.41 v1(15.76,55.27) ; 15.76,55.41 16.07,55.41 18.09,53.39 20.15,53.39 20.39,53.63 20.54,53.63 20.89,53.98 GPU1.AE9 ; v2(7.33,58.4) 7.15,58.22 GPU3.B9
DGPU_RXP_C_CPU_TXP3: length 20.8
  L6 w0.14: v2(12.56,54.28) 12.56,54.36 12.19,54.73 12.19,55.05 11.84,55.41 11.15,55.41 9.44,57.13 7.03,57.13 6.4,57.75 5.38,57.75 5.16,57.97 5.16,58.26 v2(5.4,58.5)
  BOTTOM w0.114: v2(5.4,58.5) 5.35,58.45 GPU3.B6 ; GPU1.AG9 19.32,54.26 18.3,54.26 16.25,56.32 14.82,56.32 ; v1(14.82,56.16) 14.82,56.32 ; 14.82,56.32 13.22,56.32 12.17,55.26 12.17,54.73 12.56,54.33 v2(12.56,54.28)
DGPU_TXN_CPU_RXN0: length 6.3
  TOP w0.114: v2(24.06,53.56) 24.03,53.56 23.66,53.93 23.06,53.93 23.05,53.92 22.63,54.33 21.28,54.33 20.27,53.33 19.65,53.33 19.51,53.19 C7302.2
  BOTTOM w0.114: v2(24.06,53.56) GPU1.AB9
DGPU_TXN_CPU_RXN1: length 5.2
  TOP w0.114: 20.16,54.36 20.46,54.36 20.84,54.74 22.83,54.74 v2(23.21,54.36) ; 20.16,54.36 19.48,54.36 C7304.2 ; 20.16,54.36 v1(20.16,54.21)
  BOTTOM w0.114: v2(23.21,54.36) 22.8,54.77 GPU1.AC10
DGPU_TXN_CPU_RXN2: length 4.2
  TOP w0.114: C7306.2 19.54,56.7 19.68,56.84 21.05,56.84 21.43,56.45 21.47,56.45 21.47,56.45 21.98,56.45 v2(22.39,56.04)
  BOTTOM w0.114: v2(22.39,56.04) 22.39,56.03 GPU1.AC11
DGPU_TXN_CPU_RXN3: length 5.8
  TOP w0.114: v2(23.22,56.83) 23.22,56.84 22.86,57.2 22.86,57.77 22.59,58.04 22.29,58.04 ; C7308.2 19.59,58.04 22.29,58.04 ; 22.29,58.04 v1(22.29,58.19)
  BOTTOM w0.114: GPU1.AB12 23.64,56.47 23.31,56.8 23.25,56.8 v2(23.22,56.83)
DGPU_TXP_CPU_RXP0: length 6.4
  TOP w0.114: v2(23.23,53.52) 23.1,53.52 22.53,54.09 21.38,54.09 20.37,53.09 20.08,53.09 ; v1(20.08,52.94) 20.08,53.09 ; 20.08,53.09 19.75,53.09 19.62,52.96 19.62,52.35 19.52,52.25 19.26,52.25 C7301.2
  BOTTOM w0.114: v2(23.23,53.52) 22.93,53.52 22.8,53.65 GPU1.AC9
DGPU_TXP_CPU_RXP1: length 5.2
  TOP w0.114: 21.43,54.98 22.94,54.98 23.21,55.25 v2(23.23,55.25) ; 21.43,54.98 v1(21.43,55.12) ; 21.43,54.98 20.74,54.98 20.36,54.6 19.47,54.6 C7303.2
  BOTTOM w0.114: v2(23.23,55.25) 23.23,55.19 GPU1.AB10
DGPU_TXP_CPU_RXP2: length 4.4
  TOP w0.114: C7305.2 19.26,55.71 19.52,55.71 19.65,55.83 19.65,56.47 19.78,56.59 20.21,56.59 ; v1(20.21,56.44) 20.21,56.59 ; 20.21,56.59 20.95,56.59 21.33,56.21 21.43,56.21 v2(21.6,56.04)
  BOTTOM w0.114: v2(21.6,56.04) 21.6,55.71 21.69,55.62 GPU1.AD11
DGPU_TXP_CPU_RXP3: length 5.8
  TOP w0.114: v2(22.4,56.86) 22.62,57.08 22.62,57.67 22.49,57.8 20.84,57.8 ; C7307.2 19.46,57.28 19.6,57.28 19.73,57.41 19.73,57.67 19.85,57.8 20.84,57.8 ; 20.84,57.8 v1(20.84,57.66)
  BOTTOM w0.114: v2(22.4,56.86) 22.4,56.59 22.53,56.46 GPU1.AC12
FB_CAL_PD_VDDQ: length 2.5
  TOP w0.254: v1(40.73,65) 40.71,65 40.49,65.22 R7505.1
  TOP w0.508: v2(38.98,65.11) 39.09,65.22 R7505.1
  BOTTOM w0.356: v2(38.98,65.11) 38.98,65.1 38.98,65.08 GPU1.D22
FB_CAL_PU_GND: length 2.4
  TOP w0.508: v2(39.81,65.95) 40.02,66.16 40.02,66.78 40.51,67.28 R7507.2
  BOTTOM w0.305: GPU1.C24 39.81,65.99 v2(39.81,65.95)
FB_CAL_TERM_GND: length 2.7
  TOP w0.508: v2(41.7,68.05) 41.49,67.85 R7506.1
  BOTTOM w0.127: v2(41.7,68.05) 41.27,67.62 40.68,67.62 40.26,67.2 GPU1.B25
FB_CLAM: length 5.7
  TOP w0.254: R7519.1 R7518.1 34.62,49.42 35,49.04 36.93,49.04 v2(37.31,49.42) 37.4,49.51 v1(38.01,49.51)
  BOTTOM w0.254: GPU1.F3 36.9,49.01 v2(37.31,49.42)
FB_VREF: length 1.2
  TOP w0.102: v2(38.17,65.15) 38.19,65.15 TP7503.1
  BOTTOM w0.102: GPU1.D23 38.52,65.55 38.17,65.19 v2(38.17,65.15)
FBA_CLK0_MIDPT: length 2.8
  TOP w0.114: v1(52.42,86.08) 52.09,85.75 C7801.2 52.07,85.14 R7802.2 R7801.2
FBA_CLK0N: length 45.2
  TOP w0.114: R7802.1 50.03,84.78 48.97,84.78 v2(48.89,84.86) ; v1(39.33,66.42) 39.33,66.28 v2(39.02,65.96) ; VRAM2.J11 44.81,85.6 v2(45.2,85.99)
  L3 w0.14: v2(39.02,65.96) 39.45,66.39 41.67,66.39 41.8,66.26 41.8,65.22 41.67,65.09 39.77,65.09 39.48,64.81 39.48,63.04 39.77,62.76 40.61,62.76 40.89,63.04 40.89,63.71 41.11,63.92 42.28,63.92 49.33,70.97 49.33,84.42 v2(48.89,84.86) 48.58,84.86 47.98,85.46 46.56,85.46 46.17,85.86 45.34,85.86 v2(45.2,85.99)
  BOTTOM w0.114: v2(39.02,65.96) 39.02,66.48 38.6,66.89 GPU1.D25 ; v2(45.2,85.99) 44.81,85.6 VRAM2.J11
FBA_CLK0P: length 44.3
  TOP w0.114: VRAM2.J12 45.6,85.59 v2(45.2,85.19) ; v2(48.83,84.23) 49.14,84.53 50.12,84.53 R7801.1
  L3 w0.14: v2(38.17,65.94) 38.17,66.2 38.35,66.38 39.06,66.38 39.34,66.66 41.78,66.66 42.07,66.37 42.07,65.11 41.78,64.82 39.88,64.82 39.75,64.7 39.75,63.15 39.88,63.03 40.5,63.03 40.63,63.15 40.63,63.82 41,64.19 42.17,64.19 49.06,71.08 49.06,84 v2(48.83,84.23) 47.87,85.19 46.45,85.19 46.06,85.59 45.36,85.59 45.2,85.42 v2(45.2,85.19)
  BOTTOM w0.114: GPU1.D24 38.37,66.4 38.17,66.2 v2(38.17,65.94) ; v2(45.2,85.19) 45.6,85.59 VRAM2.J12
FBA_CLK1_MIDPT: length 2.7
  TOP w0.114: R7906.2 R7908.2 10.63,83.45 C7901.2 9.86,82.72 v1(9.67,82.53)
FBA_CLK1N: length 48.3
  TOP w0.114: v2(32.36,65.13) 31.98,65.51 v1(31.98,65.55) ; v2(13.14,85.24) 12.23,84.33 R7906.1 ; v2(16.78,85.19) 17.18,85.6 VRAM3.J11
  L6 w0.14: v2(32.36,65.13) 32.36,64.33 31.55,63.52 28.07,63.52 27.07,62.51 25.26,62.51 23.88,63.89 22.69,63.89 18.19,68.39 18.19,69.59 11.18,76.6 11.18,84.47 11.81,85.11 13,85.11 v2(13.14,85.24) 13.32,85.43 13.68,85.43 14.37,86.12 16.31,86.12 16.62,85.8 16.62,85.35 v2(16.78,85.19)
  BOTTOM w0.114: GPU1.M22 32.31,65.13 v2(32.36,65.13) ; v2(16.78,85.19) 16.79,85.19 VRAM3.J11
FBA_CLK1P: length 47.8
  TOP w0.114: VRAM3.J12 16.4,85.6 v2(15.99,85.19) ; v2(13.15,84.32) 12.55,84.32 11.73,83.49 R7908.1
  L6 w0.14: v2(15.99,85.19) 16.25,85.19 16.35,85.3 16.35,85.69 16.2,85.85 14.48,85.85 13.82,85.19 13.82,84.64 13.48,84.31 13.16,84.31 v2(13.15,84.32) 13.15,84.61 12.92,84.84 11.92,84.84 11.45,84.36 11.45,76.71 18.46,69.7 18.46,68.5 22.8,64.16 23.99,64.16 25.37,62.78 26.96,62.78 27.96,63.78 31.44,63.78 32.09,64.44 32.09,64.8 31.71,65.18 v2(31.54,65.18)
  BOTTOM w0.114: GPU1.N22 31.5,64.76 31.59,64.85 31.59,65.13 v2(31.54,65.18) ; VRAM3.J12 16.4,85.6 v2(15.99,85.19)
FBA_CMD0: length 33.6
  TOP w0.114: v2(39.59,69.42) 39.64,69.37 v1(39.64,68.71) ; VRAM2.L12 46,83.6 v2(46,83.6)
  L3 w0.127: v2(39.59,69.42) 38.83,68.66 38.83,67.87 39.12,67.58 44.21,67.58 48.11,71.48 48.11,74.44 47.82,74.73 46.37,74.73 46,75.1 46,78.43 46.17,78.59 47.09,78.59 47.26,78.76 47.26,79.09 47.09,79.26 46.17,79.26 46,79.42 46,79.75 46.17,79.92 47.09,79.92 47.26,80.08 47.26,80.41 47.09,80.58 46.17,80.58 46,80.74 v2(46,83.6)
  BOTTOM w0.114: VRAM2.L12 46,83.6 v2(46,83.6) ; GPU1.C27 39.4,69.23 v2(39.59,69.42)
FBA_CMD1: length 35.4
  TOP w0.114: VRAM2.K10 43.89,84.8 v2(43.53,84.44)
  L3 w0.127: v2(40.22,69.62) 40.22,69.44 39.77,68.98 39.77,68.19 40.01,67.95 40.91,67.95 41.57,68.61 43.1,68.61 43.27,68.44 43.27,68.16 43.43,68 43.76,68 43.93,68.16 43.93,68.44 44.09,68.61 44.65,68.61 47.69,71.65 47.69,72.77 47.53,72.93 45.7,72.93 45.53,73.1 45.53,73.43 45.7,73.59 47.53,73.59 47.69,73.76 47.69,74.09 47.53,74.25 45.7,74.25 45.53,74.42 45.53,77.88 45.23,78.18 44.11,78.18 43.91,78.39 43.91,84.02 43.53,84.4 v2(43.53,84.44)
  BOTTOM w0.114: VRAM2.K10 43.89,84.8 v2(43.53,84.44) ; v2(40.22,69.62) 40.22,69.35 39.83,68.96 39.83,68.43 GPU1.C26
FBA_CMD2: length 39.4
  TOP w0.114: VRAM2.K11 44.4,85.2 v2(44.4,85.2) ; v1(38.78,67.54) 38.78,67.41 v2(38.15,66.79)
  L3 w0.127: v2(38.15,66.79) 38.18,66.79 38.55,67.16 44.39,67.16 48.53,71.3 48.53,75 48.36,75.16 46.61,75.16 46.45,75.33 46.45,75.66 46.61,75.82 48.36,75.82 48.53,75.99 48.53,76.32 48.36,76.48 46.61,76.48 46.45,76.65 46.45,76.98 46.61,77.14 48.36,77.14 48.53,77.31 48.53,81.11 48.17,81.46 47.49,81.46 47.24,81.72 47.24,83.78 46.44,84.58 45.02,84.58 v2(44.4,85.2)
  BOTTOM w0.114: VRAM2.K11 44.8,84.81 v2(44.4,85.2) ; v2(38.15,66.79) 37.76,66.4 GPU1.E24
FBA_CMD3: length 37
  TOP w0.114: VRAM2.H11 44.4,86 v2(44.4,85.99) ; v2(37.36,66.8) 37.1,67.06 v1(36.64,67.06)
  L3 w0.127: v2(37.36,66.8) 37.73,67.17 37.73,68.56 39.18,70.01 39.72,70.01 39.8,70.09 41,70.09 42.05,69.04 44.49,69.04 45.1,69.65 45.1,70.16 45.27,70.33 45.77,70.33 45.94,70.49 45.94,70.82 45.77,70.99 45.27,70.99 45.1,71.15 45.1,71.53 45.27,71.69 47.07,71.69 47.23,71.86 47.23,72.19 47.07,72.35 45.27,72.35 45.1,72.52 45.1,77.55 44.87,77.78 43.42,77.78 43.01,78.19 43.01,84.61 v2(44.4,85.99)
  BOTTOM w0.114: GPU1.F24 36.96,66.4 v2(37.36,66.8) ; VRAM2.H11 44.8,86.39 v2(44.4,85.99)
FBA_CMD4: length 33.6
  TOP w0.114: v2(43.42,86.5) 43.51,86.4 VRAM2.H10
  L3 w0.127: v2(39.54,70.45) 39.83,70.74 42.01,70.74 42.13,70.62 42.13,69.64 42.3,69.47 42.63,69.47 42.79,69.64 42.79,70.64 42.92,70.77 43.33,70.77 43.45,70.64 43.45,69.64 43.62,69.47 43.95,69.47 44.12,69.64 44.12,70.29 44.68,70.85 44.68,75.91 44.52,76.07 43.13,76.07 42.97,76.24 42.97,76.57 43.13,76.73 44.52,76.73 44.68,76.9 44.68,77.21 44.44,77.45 43.34,77.45 42.72,78.07 42.72,86.27 42.94,86.5 v2(43.42,86.5)
  BOTTOM w0.114: v2(43.42,86.5) 43.51,86.4 VRAM2.H10 ; v2(39.54,70.45) 38.78,69.7 38.78,68.98 GPU1.D27
FBA_CMD5: length 34.7
  TOP w0.114: v2(45.2,86.8) 45.2,86.8 VRAM2.G12
  L3 w0.127: v2(39.54,71.2) 43.86,71.2 44.26,71.61 44.26,75.49 44.11,75.64 42.9,75.64 42.52,76.03 42.52,77.62 42.43,77.71 42.43,87.81 42.55,87.94 43.71,87.94 43.88,87.77 43.88,87.49 44.04,87.33 44.37,87.33 44.54,87.49 44.54,87.77 44.7,87.94 46.29,87.94 46.42,87.81 46.42,87.37 46.29,87.24 45.32,87.24 45.2,87.12 v2(45.2,86.8)
  BOTTOM w0.114: GPU1.D26 39.03,68.43 39.03,69.44 39.57,69.99 39.66,69.99 39.95,70.28 39.95,70.79 v2(39.54,71.2) ; VRAM2.G12 45.6,87.2 v2(45.2,86.8)
FBA_CMD6: length 37.8
  TOP w0.114: v2(39.6,86.8) 39.6,86.8 VRAM2.H4
  L3 w0.127: v2(39.6,86.8) 38.36,85.56 37.82,85.56 37.66,85.72 37.01,85.72 36.5,85.2 34.31,85.2 34.05,85.46 34.05,89.56 33.92,89.69 33.38,89.69 33.26,89.56 33.26,84.9 33.63,84.52 33.63,76.04 33.99,75.68 34.78,75.68 36.71,73.75 36.71,71.68 v2(36.64,71.61)
  BOTTOM w0.114: VRAM2.H4 39.2,86.4 v2(39.6,86.8) ; v2(36.64,71.61) 36.64,71.4 37.89,70.15 37.89,68.74 37.4,68.25 37.4,68.01 36.9,67.51 GPU1.F25
FBA_CMD7: length 35.1
  TOP w0.114: v2(37.48,68.94) 37.43,68.89 v1(37.43,68.33) ; v2(40.45,86.85) 40.01,86.4 VRAM2.H5
  L3 w0.127: v2(37.48,68.94) 39.1,70.56 39.1,71.42 39.32,71.64 43.7,71.64 43.84,71.78 43.84,73.69 43.7,73.83 42.32,73.83 42.15,73.99 42.15,74.32 42.32,74.49 43.7,74.49 43.83,74.62 43.83,75.09 43.7,75.21 42.36,75.21 42.1,75.47 42.1,77.5 42.14,77.54 42.14,86.31 41.87,86.57 41.87,88.27 41.75,88.4 41.21,88.4 41.09,88.27 41.09,86.97 40.96,86.85 v2(40.45,86.85)
  BOTTOM w0.114: VRAM2.H5 40.01,86.4 v2(40.45,86.85) ; v2(37.48,68.94) 37.48,68.89 36.9,68.31 GPU1.F26
FBA_CMD8: length 38.3
  TOP w0.114: VRAM2.J4 39.24,85.64 39.24,85.65 v2(39.6,86)
  L3 w0.127: v2(37.34,66) 36.92,66.42 36.92,66.98 36.97,67.03 36.97,69.09 38.81,70.93 38.81,71.72 39.15,72.06 43.29,72.06 43.42,72.19 43.42,72.6 43.3,72.72 38.98,72.72 38.85,72.85 38.85,73.26 38.98,73.38 41.55,73.38 41.68,73.51 41.68,73.92 41.55,74.04 40.6,74.04 40.48,74.17 40.48,74.58 40.6,74.7 41.55,74.7 41.68,74.83 41.68,77.57 41.84,77.73 41.84,85.62 41.46,86 v2(39.6,86)
  BOTTOM w0.114: VRAM2.J4 39.2,85.61 v2(39.6,86) ; v2(37.34,66) 36.94,65.6 GPU1.F23
FBA_CMD9: length 38.6
  TOP w0.114: v2(36.49,65.16) 36.9,64.75 v1(36.9,64.72) ; v2(40.48,85.14) 40.02,85.6 VRAM2.J5
  L3 w0.127: v2(40.48,85.14) 40.68,85.14 41.26,84.57 41.26,79.21 39.8,77.76 39.8,77.2 39.5,76.9 39.5,75.85 39.27,75.62 38.89,75.62 37.51,77 37.51,80.57 37.38,80.7 36.97,80.7 36.85,80.57 36.85,78.22 36.68,78.06 36.32,78.06 36.16,77.89 36.16,77.56 36.32,77.39 36.68,77.39 36.85,77.23 36.85,76.9 36.68,76.73 36.32,76.73 36.16,76.57 36.16,76.17 37.97,74.36 37.97,70.96 36.39,69.38 36.39,67.29 36.12,67.02 36.12,66.6 36.07,66.55 36.07,65.58 v2(36.49,65.16)
  BOTTOM w0.114: VRAM2.J5 40.02,85.6 v2(40.48,85.14) ; v2(36.49,65.16) 36.1,64.76 GPU1.G22
FBA_CMD10: length 38
  TOP w0.114: VRAM2.K4 39.2,84.81 v2(39.59,85.2) ; v2(36.51,66) 36.4,65.89 v1(35.85,65.89)
  L3 w0.127: v2(36.51,66) 36.51,67 36.68,67.17 36.68,69.25 37.13,69.71 38.39,70.97 38.39,73.66 38.56,73.83 39.84,73.83 39.97,73.96 39.97,74.37 39.84,74.5 38.42,74.5 36.84,76.07 36.84,76.25 37.14,76.55 37.37,76.55 38.75,75.16 39.79,75.16 39.92,75.29 39.92,76.41 40.05,76.53 40.45,76.53 40.58,76.41 40.58,75.29 40.71,75.16 41.13,75.16 41.26,75.29 41.26,77.2 41.09,77.36 40.71,77.36 40.58,77.49 40.58,77.89 40.71,78.02 41.28,78.02 41.55,78.3 41.55,85.19 41.16,85.58 39.97,85.58 v2(39.59,85.2)
  BOTTOM w0.114: GPU1.G23 36.11,65.6 v2(36.51,66) ; VRAM2.K4 39.2,84.81 v2(39.59,85.2)
FBA_CMD11: length 37.6
  TOP w0.114: VRAM2.K5 40.06,84.8 v2(40.48,84.38)
  L3 w0.127: v2(40.48,84.38) 40.06,83.97 40.06,81.42 40.4,81.08 40.61,81.08 40.91,80.78 40.91,79.28 39.39,77.75 39.39,77.38 38.95,76.95 38.41,76.95 37.96,77.4 37.96,82.84 37.48,83.32 36.79,83.32 36.59,83.12 36.08,83.12 35.7,82.74 35.7,76.03 37.55,74.18 37.55,71.08 36.09,69.62 36.09,67.41 35.68,67 v2(35.68,66.78)
  BOTTOM w0.114: v2(35.68,66.78) 35.72,66.78 GPU1.G24 ; VRAM2.K5 40.06,84.8 v2(40.48,84.38)
FBA_CMD12: length 35.3
  TOP w0.114: VRAM2.L3 38.8,84.4 v2(38.8,84.4)
  L3 w0.127: v2(38.8,84.4) 39.02,84.18 39.02,83.66 38.78,83.42 38.09,83.42 37.66,83.85 37.15,83.85 37.03,83.97 37.02,83.97 36.73,84.26 34.25,84.26 34.13,84.13 34.13,83.59 34.25,83.47 35.16,83.47 35.28,83.34 35.28,82.75 35.12,82.59 34.22,82.59 34.05,82.42 34.05,82.09 34.22,81.92 35.12,81.92 35.28,81.76 35.28,81.43 35.12,81.26 34.22,81.26 34.05,81.1 34.05,80.77 34.22,80.6 35.12,80.6 35.28,80.44 35.28,80.11 35.12,79.94 34.22,79.94 34.05,79.78 34.05,79.45 34.22,79.28 35.12,79.28 35.28,79.12 35.28,78.79 35.12,78.62 34.22,78.62 34.05,78.46 34.05,78.13 34.22,77.96 35.12,77.96 35.28,77.8 35.28,77.47 35.12,77.3 34.22,77.3 34.05,77.14 34.05,76.81 34.22,76.64 35.12,76.64 35.28,76.48 35.28,75.86 37.13,74.01 37.13,71.48 36.8,71.14 36.76,71.14 v2(36.54,70.92)
  BOTTOM w0.114: GPU1.F27 36.9,70.56 36.57,70.89 36.54,70.92 v2(36.54,70.92) ; v2(38.8,84.4) 38.78,84.38 38.78,84.38 VRAM2.L3
FBA_CMD13: length 41
  TOP w0.114: VRAM2.J2 37.25,85.95 36.45,85.95 v2(36.15,85.66)
  L3 w0.127: v2(36.15,85.66) 34.96,85.66 34.47,86.15 34.47,90.13 34.31,90.3 33.71,90.3 33.52,90.49 33.52,90.76 33.71,90.96 34.31,90.96 34.47,91.12 34.47,91.44 34.27,91.65 33.04,91.65 32.84,91.44 32.84,84.72 33.21,84.35 33.21,75.86 33.81,75.26 34.6,75.26 36.19,73.68 36.19,72.24 v2(36.24,72.19)
  BOTTOM w0.114: GPU1.G25 36.1,67.48 36.45,67.83 36.45,70.43 36.13,70.75 36.13,71.18 36.2,71.26 36.2,72.16 v2(36.24,72.19) 35.61,72.19 R7520.2 ; v2(36.15,85.66) 36.45,85.95 37.25,85.95 VRAM2.J2
FBA_CMD14: length 39.7
  TOP w0.114: v2(38,86) 38.4,85.6 VRAM2.J3 ; v2(35.71,86.11) 35.27,85.68 v1(34.41,85.68) R7516.1
  L3 w0.127: v2(35.78,71.45) 35.64,71.59 35.64,73.63 34.43,74.84 33.64,74.84 32.79,75.69 32.79,84.17 32.42,84.55 32.42,91.9 32.62,92.1 34.69,92.1 34.89,91.9 34.89,86.93 v2(35.71,86.11) 37.88,86.11 v2(38,86)
  BOTTOM w0.114: v2(38,86) 38.4,85.6 VRAM2.J3 ; GPU1.G27 36.1,70.43 35.88,70.65 35.88,71.35 v2(35.78,71.45)
FBA_CMD15: length 38.7
  TOP w0.114: v2(38.8,86.8) 38.4,87.2 VRAM2.G3
  L3 w0.127: v2(35.54,70.42) 35.54,70.58 35.22,70.89 35.22,71.42 35.22,71.42 35.22,73.46 34.25,74.43 33.47,74.43 32.38,75.52 32.38,84 32,84.38 32,92.07 32.45,92.52 35.16,92.52 35.84,91.84 35.84,91.39 36.08,91.14 36.46,91.14 36.76,90.84 36.76,87.99 37.1,87.66 37.95,87.66 v2(38.8,86.8)
  BOTTOM w0.114: v2(38.8,86.8) 38.4,87.2 VRAM2.G3 ; GPU1.G26 36.1,68.31 35.75,68.66 35.75,69.27 35.8,69.32 35.8,70.17 v2(35.54,70.42)
FBA_CMD16: length 37.5
  TOP w0.114: v2(31.55,68.4) 31.66,68.51 v1(32.27,68.51) ; VRAM3.G12 16.8,84.4 v2(16.8,84.4)
  L3 w0.127: v2(31.55,68.4) 31.3,68.65 31.24,68.65 30.59,69.29 29.3,69.29 28.69,69.9 24.09,69.9 22.97,71.02 22.13,71.02 16.32,76.84 16.32,78.28 16.15,78.45 15,78.45 14.87,78.58 14.87,78.98 15,79.11 16.15,79.11 16.32,79.27 16.32,79.6 16.15,79.77 14.9,79.77 14.77,79.9 14.77,80.3 14.9,80.43 16.15,80.43 16.32,80.59 16.32,81.01 16.15,81.17 15.88,81.17 15.71,81.34 15.71,81.67 15.88,81.83 16.15,81.83 16.32,82 16.32,82.33 16.15,82.49 15.88,82.49 15.71,82.66 15.71,82.99 15.88,83.16 16.15,83.16 16.32,83.32 16.32,83.91 v2(16.8,84.4)
  BOTTOM w0.114: v2(16.8,84.4) 16.78,84.38 16.78,84.38 VRAM3.G12 ; v2(31.55,68.4) 31.55,68.39 31.56,68.38 31.56,66.78 GPU1.M24
FBA_CMD17: length 40.1
  TOP w0.114: VRAM3.H10 18.18,84.8 v2(18.48,85.09)
  L3 w0.127: v2(18.48,85.09) 18.13,85.45 18.13,86.31 17.95,86.49 17.29,86.49 17.07,86.27 14.13,86.27 13.61,85.76 13.61,84.16 13.2,83.74 13.2,78.77 21.78,70.18 22.62,70.18 23.18,69.62 23.18,68.84 23.92,68.1 30.81,68.1 31.54,67.37 v2(31.54,65.99)
  BOTTOM w0.114: v2(18.48,85.09) 18.18,84.8 VRAM3.H10 ; GPU1.M23 31.93,65.6 v2(31.54,65.99)
FBA_CMD18: length 39.4
  TOP w0.114: VRAM3.H11 17.2,84.81 v2(17.59,85.2) ; v1(32.63,67.16) 32.84,67.16 v2(33.2,66.79)
  L3 w0.127: v2(17.59,85.2) 19.09,83.71 19.09,77.72 18.93,77.55 17.16,77.55 17.03,77.42 17.03,77.02 17.16,76.89 18.84,76.89 18.96,76.76 18.96,76.36 18.84,76.23 18.18,76.23 18.05,76.1 18.05,75.7 18.18,75.57 19.01,75.57 19.31,75.27 19.31,75.04 19.14,74.87 19.14,74.63 19.37,74.4 19.6,74.4 19.78,74.57 20.01,74.57 20.24,74.34 20.24,74.11 20.07,73.93 20.07,73.7 20.31,73.47 20.54,73.47 20.71,73.64 20.95,73.64 21.18,73.4 21.18,73.17 21.01,73 21.01,72.76 21.24,72.53 21.47,72.53 21.65,72.7 21.88,72.7 22.11,72.47 22.11,72.24 21.94,72.06 21.94,71.83 22.17,71.6 22.41,71.6 22.58,71.77 22.81,71.77 24.37,70.22 30.35,70.22 30.6,69.96 30.6,69.73 31.39,68.94 31.63,68.94 31.73,68.84 32.3,68.27 32.3,67.7 v2(33.2,66.79)
  BOTTOM w0.114: VRAM3.H11 17.2,84.81 v2(17.59,85.2) ; GPU1.K24 33.24,66.78 33.22,66.78 v2(33.2,66.79)
FBA_CMD19: length 39
  TOP w0.114: v2(17.59,85.98) 17.2,86.37 VRAM3.K11
  L3 w0.127: v2(17.59,85.98) 17.41,85.8 14.41,85.8 13.9,85.29 13.9,84.04 13.8,83.93 13.8,78.76 21.96,70.6 22.8,70.6 23.69,69.71 23.69,69.04 24.04,68.68 26.08,68.68 26.24,68.85 26.24,69.31 26.41,69.47 26.74,69.47 26.9,69.31 26.9,68.85 27.07,68.68 29.4,68.68 29.72,69 30.44,69 30.7,68.74 30.7,68.62 31.11,68.21 32.68,66.64 32.68,66.52 v2(33.2,65.99)
  BOTTOM w0.114: VRAM3.K11 17.2,86.37 v2(17.59,85.98) ; v2(33.2,65.99) 33.6,65.6 GPU1.K23
FBA_CMD20: length 37.1
  TOP w0.114: VRAM3.K10 18.72,86.4 v2(18.79,86.46) ; v2(31.55,69.4) 31.08,68.92 v1(31.08,68.76)
  L3 w0.127: v2(31.55,69.4) 31.53,69.4 30.9,70.03 30.9,70.08 30.31,70.67 24.53,70.67 24.12,71.08 24.12,71.31 24.6,71.79 24.6,72.02 24.36,72.25 24.13,72.25 23.65,71.78 23.42,71.78 23.18,72.01 23.18,72.24 23.66,72.72 23.66,72.95 23.43,73.19 23.19,73.19 22.72,72.71 22.48,72.71 22.25,72.94 22.25,73.18 22.73,73.65 22.73,73.89 22.49,74.12 22.26,74.12 21.78,73.64 21.55,73.64 21.31,73.88 21.31,74.11 21.79,74.59 21.79,74.82 21.56,75.06 21.33,75.06 20.85,74.58 20.61,74.58 20.38,74.81 20.38,75.05 20.86,75.52 20.86,75.76 20.62,75.99 20.39,75.99 19.91,75.51 19.68,75.51 19.38,75.81 19.38,85.62 18.79,86.22 v2(18.79,86.46)
  BOTTOM w0.114: v2(18.79,86.46) 18.72,86.4 VRAM3.K10 ; v2(31.55,69.4) 31.55,69.2 31.94,68.82 GPU1.M27
FBA_CMD21: length 37.6
  TOP w0.114: v2(16.8,86.8) 16.4,87.2 VRAM3.L12
  L3 w0.127: v2(16.8,86.8) 18.51,86.8 18.94,87.24 18.94,88.95 19.17,89.18 19.62,89.18 19.8,89 19.8,77.45 20.13,77.12 20.37,77.12 20.57,77.33 20.81,77.33 21.04,77.09 21.04,76.86 20.83,76.65 20.83,76.42 21.07,76.18 21.3,76.18 21.51,76.39 21.74,76.39 21.97,76.16 21.97,75.92 21.77,75.72 21.77,75.48 22,75.25 22.23,75.25 22.44,75.46 22.67,75.46 22.91,75.22 22.91,74.99 22.7,74.78 22.7,74.55 26.15,71.1 30.29,71.1 31.36,70.03 31.51,70.03 v2(31.51,70.03)
  BOTTOM w0.114: VRAM3.L12 16.4,87.2 v2(16.8,86.8) ; GPU1.M26 32.04,68.1 32.04,68.41 32.29,68.66 32.29,68.94 32.25,68.99 32.25,69.3 v2(31.51,70.03)
FBA_CMD22: length 38.4
  TOP w0.114: VRAM3.K4 22.4,86 v2(22.4,85.99)
  L3 w0.127: v2(33.01,70.63) 32.79,70.63 32.08,71.35 32.02,71.35 31.59,71.77 31.59,71.87 30.42,73.04 30.19,73.04 29.92,72.77 29.68,72.77 29.45,73.01 29.45,73.24 29.72,73.51 29.72,73.75 29.52,73.95 29.29,73.95 28.51,73.17 28.27,73.17 28.04,73.4 28.04,73.63 28.82,74.41 28.82,74.65 26.91,76.55 26.91,80.17 26.74,80.34 26.36,80.34 26.21,80.2 26.21,77.71 25.9,77.4 24.12,77.4 23.96,77.56 23.96,78.12 23.79,78.29 23.46,78.29 23.3,78.12 23.3,77.85 23.15,77.7 22.8,77.7 21.01,79.49 21.01,81.75 21.92,82.65 21.92,83.43 22.48,83.99 22.48,85.8 22.4,85.87 v2(22.4,85.99)
  BOTTOM w0.114: GPU1.M25 32.36,67.62 32.36,68.38 32.53,68.56 32.53,69.05 32.49,69.08 32.49,70.02 33.01,70.53 v2(33.01,70.63) ; v2(22.4,85.99) 22.8,86.39 VRAM3.K4
FBA_CMD23: length 36.2
  TOP w0.114: v2(21.55,86.74) 21.66,86.74 VRAM3.K5
  L3 w0.127: v2(33.06,69.85) 33.06,69.93 31.94,71.05 31.74,71.05 31.17,71.62 31.17,71.7 30.62,72.25 28.53,72.25 27.3,73.48 27.3,73.72 28.09,74.51 28.09,74.75 27.86,74.98 27.62,74.98 26.83,74.19 26.6,74.19 26.36,74.42 26.36,74.65 27.16,75.45 27.16,75.68 26.92,75.92 26.69,75.92 25.89,75.12 25.66,75.12 25.43,75.35 25.43,75.59 26.22,76.38 26.22,76.62 25.99,76.85 25.76,76.85 24.96,76.05 24.73,76.05 24.45,76.33 24.45,76.81 24.32,76.94 22.97,76.94 20.72,79.19 20.72,83.98 21.05,84.31 21.54,84.31 22.18,84.95 22.18,85.59 21.96,85.81 21.96,86.34 v2(21.55,86.74)
  BOTTOM w0.114: GPU1.K26 33.62,68.1 33.27,68.45 33.27,68.99 33.32,69.03 33.32,69.45 33.06,69.71 v2(33.06,69.85) ; VRAM3.K5 21.95,86.4 21.61,86.74 v2(21.55,86.74)
FBA_CMD24: length 40.5
  TOP w0.114: v1(34.92,65.08) 34.15,65.08 v2(34.03,65.2) ; v2(23.2,85.99) 22.81,85.6 VRAM3.J4
  L3 w0.127: v2(23.2,85.99) 23.2,85.81 22.77,85.38 22.77,83.87 22.76,83.86 22.76,83.24 22.89,83.11 23.59,83.11 23.71,82.99 23.71,82.51 23.88,82.34 25.16,82.34 25.29,82.21 25.29,81.81 25.16,81.68 23.88,81.68 23.71,81.52 23.71,81 23.84,80.87 24.34,80.87 24.5,80.7 24.5,80.37 24.34,80.21 23.83,80.21 23.66,80.04 23.66,79.3 23.84,79.12 25.11,79.12 25.24,79.25 25.24,80.54 25.56,80.87 27.06,80.87 27.33,80.59 27.33,76.73 32.01,72.05 32.01,71.95 32.53,71.43 32.82,71.43 33.66,70.6 33.66,69.13 34.03,68.75 34.27,68.75 34.61,69.09 34.84,69.09 35.07,68.86 35.07,68.62 34.74,68.29 34.74,68.05 35.04,67.75 35.04,65.59 34.66,65.2 v2(34.03,65.2)
  BOTTOM w0.114: v2(34.03,65.2) 34.03,65.17 GPU1.K22 ; VRAM3.J4 22.81,85.6 v2(23.2,85.99)
FBA_CMD25: length 39.2
  TOP w0.114: v2(21.52,86.01) 21.93,85.6 VRAM3.J5 ; v1(34.69,66.28) 34.31,66.28 v2(34.02,65.99)
  L3 w0.127: v2(21.52,86.01) 21.56,85.97 21.56,85.8 21.89,85.47 21.89,85.07 21.58,84.76 20.79,84.76 20.43,84.4 20.43,78.89 23.66,75.66 23.89,75.66 24.11,75.88 24.29,75.88 24.58,75.59 24.58,75.42 23.89,74.73 23.89,74.55 24.18,74.26 24.36,74.26 25.02,74.92 25.2,74.92 25.48,74.64 25.48,74.46 24.84,73.81 24.84,73.63 25.13,73.34 25.31,73.34 25.98,74.01 26.16,74.01 26.44,73.73 26.44,73.55 25.77,72.88 25.77,72.7 26.06,72.41 26.24,72.41 26.9,73.07 27.08,73.07 27.37,72.78 27.37,72.6 27.16,72.39 27.16,72.16 27.48,71.83 30.45,71.83 31.52,70.76 31.82,70.76 32.46,70.11 32.46,69.04 32.72,68.78 33.19,68.78 34.46,67.51 34.46,66.56 34.02,66.12 v2(34.02,65.99)
  BOTTOM w0.114: VRAM3.J5 21.93,85.6 v2(21.52,86.01) ; GPU1.J23 34.38,65.6 34.03,65.95 34.03,65.99 v2(34.02,65.99)
FBA_CMD26: length 37.5
  TOP w0.114: v2(23.21,85.2) 23.2,85.2 VRAM3.H4
  L3 w0.127: v2(23.21,85.2) 23.8,84.6 24.11,84.6 24.73,85.22 25.32,85.22 25.66,85.56 26.44,85.56 26.66,85.78 26.66,87.28 26.78,87.4 27.19,87.4 27.32,87.28 27.32,85.83 27.44,85.7 27.88,85.7 28.01,85.83 28.01,87.25 28.13,87.38 28.65,87.38 28.78,87.25 28.78,81.1 28.62,80.93 28.35,80.93 28.18,80.77 28.18,80.44 28.35,80.27 28.62,80.27 28.78,80.11 28.78,79.78 28.62,79.61 28.35,79.61 28.18,79.45 28.18,79.12 28.35,78.95 28.62,78.95 28.78,78.79 28.78,78.46 28.62,78.29 28.35,78.29 28.18,78.13 28.18,77.8 28.35,77.63 28.62,77.63 28.78,77.47 28.78,76.49 32.94,72.33 32.94,71.82 34.36,70.4 34.45,70.4 v2(34.64,70.21)
  BOTTOM w0.114: VRAM3.H4 22.81,84.81 22.81,84.81 v2(23.21,85.2) ; v2(34.64,70.21) 34.95,69.9 34.95,69.11 35.01,69.05 35.01,68.56 34.77,68.31 34.77,67.86 34.42,67.51 GPU1.J25
